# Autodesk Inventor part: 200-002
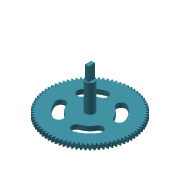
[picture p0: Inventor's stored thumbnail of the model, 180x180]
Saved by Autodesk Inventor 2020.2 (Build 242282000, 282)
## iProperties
Manager: www.cadconsulting.pl
Company: Fabian Stasiak CAD Consulting
CustomPartVersion: 1
Created: 2014-01
Part Number: 200-002
Material: Steel
Document SubType Name: Modeling
Designer: F.Stasiak
Categories: <?xml version="1.0" encoding="UTF-16"?> <MemberInstance><Categories><FamilyTemplate><FamilyTemplateParameter ValueType="xs:double" Id="1" ObjectReferenceKey="da
Density: 1 g/cm^3
Appearance: Niebieska z odcieniem szarości
Author: F.Stasiak
Subject: Zbiór ćwiczeń. Autodesk Inventor 2020. Kurs podstawowy
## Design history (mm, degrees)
sketch "Sketch1"
  geometry: C1 r 91.567 at (0, 0)
  constraints: 1 centre point
  dimensions: "d0" = 183.13444 diameter of C1 (= da_da)
extrude "Extrusion1" new body sketch "Sketch1" distance "d1" = 10 (= da_b); taper "d2" = 0 deg
workplane "Work Plane2"
sketch "Sketch2"
  geometry: C1 r 91.567 at (0, 0) reference; C2 r 90.1 at (0, 0)
  constraints: 1 centre point, 1 coincident
  dimensions: "d3" = 180.20034 diameter of C2 (= da_dw)
feature "Średnica podziałowa" sketch "Sketch2" dims "d4" = 10, "d5" = 0
workplane "Work Plane8"
workplane "Work Plane9"
feature "Przekładnia walcowa" dims "da_b" = 10, "da_d" = 180, "da_aw" = 112.62521, "da_da" = 183.13444, "da_df" = 173.01049, "da_dw" = 180.20034, angle "da_beta" = 0 deg, "da_lefttooth" = 0, "da_righttooth" = 0
sketch "Szkic3"
  geometry: C1 r 10 at (0, 0); A1 r 91.567 centre (0, 0) between (-6.288, 91.351) and (-8.08, 91.21) reference
  constraints: 1 centre point, 1 coincident
  dimensions: "d49" = 20 diameter of C1
extrude "Wyciągnięcie proste2" join sketch "Szkic3" distance "d50" = 60; taper "d51" = 0 deg
sketch "Szkic4"
  geometry: L1 (-4, -7)-(4, -7); L2 (4, -7)-(4, 7); L3 (4, 7)-(-4, 7); L4 (-4, 7)-(-4, -7); L5 (-4, -7)-(4, 7); L6 (4, -7)-(-4, 7); C1 r 10 at (0, 0) reference
  constraints: 12 end point, 2 midpoint, 2 parallel, 1 horizontal, 1 perpendicular
  dimensions: "d52" = 8 distance of L3.end L2.end; "d53" = 14 distance of L2.end L1.end
extrude "Wyciągnięcie proste3" join sketch "Szkic4" distance "d54" = 30; taper "d55" = 0 deg
sketch "Szkic5"
  geometry: L1 (0, 0)-(17.101, 46.985); L2 (0, 0)-(43.301, 25); L3 (0, -128.239)-(0, 128.239) reference; A1 r 86.505 centre (0, 0) between (11.01, 85.802) and (9.324, 86.001) reference; A2 r 50 centre (0, 0) between (43.301, 25) and (17.101, 46.985); A3 r 60 centre (0, 0) between (51.962, 30) and (20.521, 56.382); A4 r 40 centre (0, 0) between (34.641, 20) and (13.681, 37.588); A5 r 10 centre (43.301, 25) between (34.641, 20) and (51.962, 30); A6 r 10 centre (17.101, 46.985) between (20.521, 56.382) and (13.681, 37.588)
  constraints: 10 point on circle, 5 centre point, 4 end point, 4 tangent, 1 coincident
  dimensions: "d56" = 50 radius of A2; "d57" = 10 radius of A5; "d58" = 40 deg angle of L2 L1; "d59" = 20 deg angle of L3 L1
extrude "Wyciągnięcie proste4" cut sketch "Szkic5" extent not by distance; stored distance "d60" = 10; taper "d61" = 0 deg
pattern_circular "Szyk kołowy1" dims angle "d63" = 360 deg
body "Solid1"
body "Srf1"
other parameters: "d16" = 112.62521 (= da_aw), "d17" = 0, "d34" = 0.3927 (computed from da_z), "d39" = 0, "d41" = 0, "d43" = 112.62521 (= da_aw), "d46" = 112.62521 (= da_aw), "d47" = 0, "d48" = 0
